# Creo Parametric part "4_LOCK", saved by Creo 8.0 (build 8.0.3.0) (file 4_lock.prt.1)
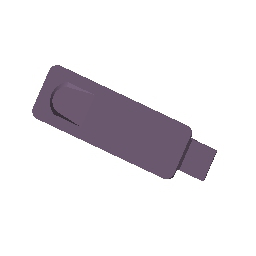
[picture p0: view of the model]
Units: millimeter Newton Second (mmNs); MM, TONNE, SECS

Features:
  1. datum plane "RIGHT"
  2. datum plane "TOP"
  3. datum plane "FRONT"
  4. coordinate system
  5. protrusion
  6. cut
  7. protrusion
  8. protrusion
  9. cut
  10. round
  11. protrusion
  12. cut
  13. protrusion
  14. round
  15. cut

Other named items: COPIED_GROUP

Layers: 0_ALL_AXIS, 0_ALL_CSYS, 0_ALL_CURVES, 0_ALL_PLANES, 0_ALL_POINTS, 0_ALL_SURFS, LOCK

Surfaces: 24 plane, 4 cylinder, 1 ruled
